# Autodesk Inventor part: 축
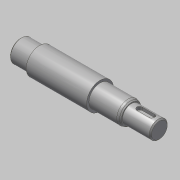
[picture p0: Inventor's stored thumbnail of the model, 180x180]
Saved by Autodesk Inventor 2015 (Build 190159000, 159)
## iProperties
Created: 2016-06
Part Number: 축
Material: 강철, 연강
Document SubType Name: Modeling
Designer: mduedu
Density: 7.86 g/cm^3
Appearance: 강철
Author: mduedu
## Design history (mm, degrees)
sketch "스케치1"
  geometry: L1 (-62, 0)-(62, 0); L2 (-62, 0)-(-62, 10); L3 (-62, 10)-(-45, 10); L4 (-45, 10)-(-45, 12); L5 (-45, 12)-(9, 12); L6 (9, 12)-(9, 10); L7 (9, 10)-(37, 10); L8 (37, 10)-(37, 8); L9 (37, 8)-(62, 8); L10 (62, 8)-(62, 0); 2 further points
  constraints: 20 end point, 5 parallel, 2 perpendicular, 1 coincident, 1 collinear, 1 horizontal, 1 midpoint, 1 vertical
  dimensions: "d0" = 124 distance of L1.start L1.end; "d2" = 16 diameter of L9 L1; "d3" = 20 diameter of L7 L1; "d4" = 24 diameter of L5 L1; "d5" = 20 diameter of L3 L1; "d6" = 17 distance of L2.end L3.end; "d7" = 25 distance of L8.end L9.end; "d8" = 53 distance from line of L5.end L10
revolve "회전1" sketch "스케치1" stored, may be unused: angle "d9" = 90 deg
chamfer "모따기1" distance "d10" = 2; stored, may be unused: second distance "d11" = 2, angle "d12" = 30 deg
fillet "모깎기1" dims "d13" = 4
node "작업 평면1"
sketch "스케치2"
  geometry: L1 (-5, 2.5)-(6, 2.5); L2 (6, -2.5)-(-5, -2.5); L3 (-5, 0)-(6, 0); L4 (-12.5, 8.845)-(-12.5, -8.845) reference; A1 r 2.5 centre (-5, 0) between (-5, 2.5) and (-5, -2.5); A2 r 2.5 centre (6, 0) between (6, -2.5) and (6, 2.5); 1 further point
  constraints: 6 end point, 4 point on circle, 3 tangent, 2 centre point, 2 parallel, 1 horizontal, 1 horizontal alignment
  dimensions: "d14" = 5 distance edge to line of A1 L4; "d15" = 5 distance between parallel lines of L2 L1; "d16" = 16 dimension on A2 A1
extrude "돌출1" cut sketch "스케치2" distance "d17" = 3; taper "d18" = 0 deg
chamfer "모따기2" distance "d19" = 1; stored, may be unused: second distance "d20" = 2, angle "d21" = 30 deg
sketch "스케치3"
  geometry: L1 (-37, -8)-(-61, -8) reference; L2 (-62, -7)-(-62, 7) reference; L3 (-38.5, -8)-(-40, -6.5); L4 (-40, -6.5)-(-40, -8); L5 (-38.5, -8)-(-40, -8); 1 further point
  constraints: 6 end point, 2 point on line, 1 collinear, 1 vertical
  dimensions: "d22" = 45 deg angle of L4 L3; "d23" = 22 distance between parallel lines of L2 L4; "d24" = 3 diameter of L3.start L4
revolve "회전2" stored, may be unused: angle "d25" = 90 deg
node "작업점1"
sketch "스케치4"
  geometry: 1 further point
hole "구멍1" sketch "스케치4" at (0, 0) diameter "d26" = 3.242; stored, may be unused: countersink angle "d30" = 90 deg, drill point angle "d32" = 120 deg; dims "d27" = 8, "d28" = 4, "d29" = 2, "d31" = 11
chamfer "모따기3" distance "d33" = 2; stored, may be unused: second distance "d34" = 2, angle "d35" = 30 deg
node "솔리드1"
